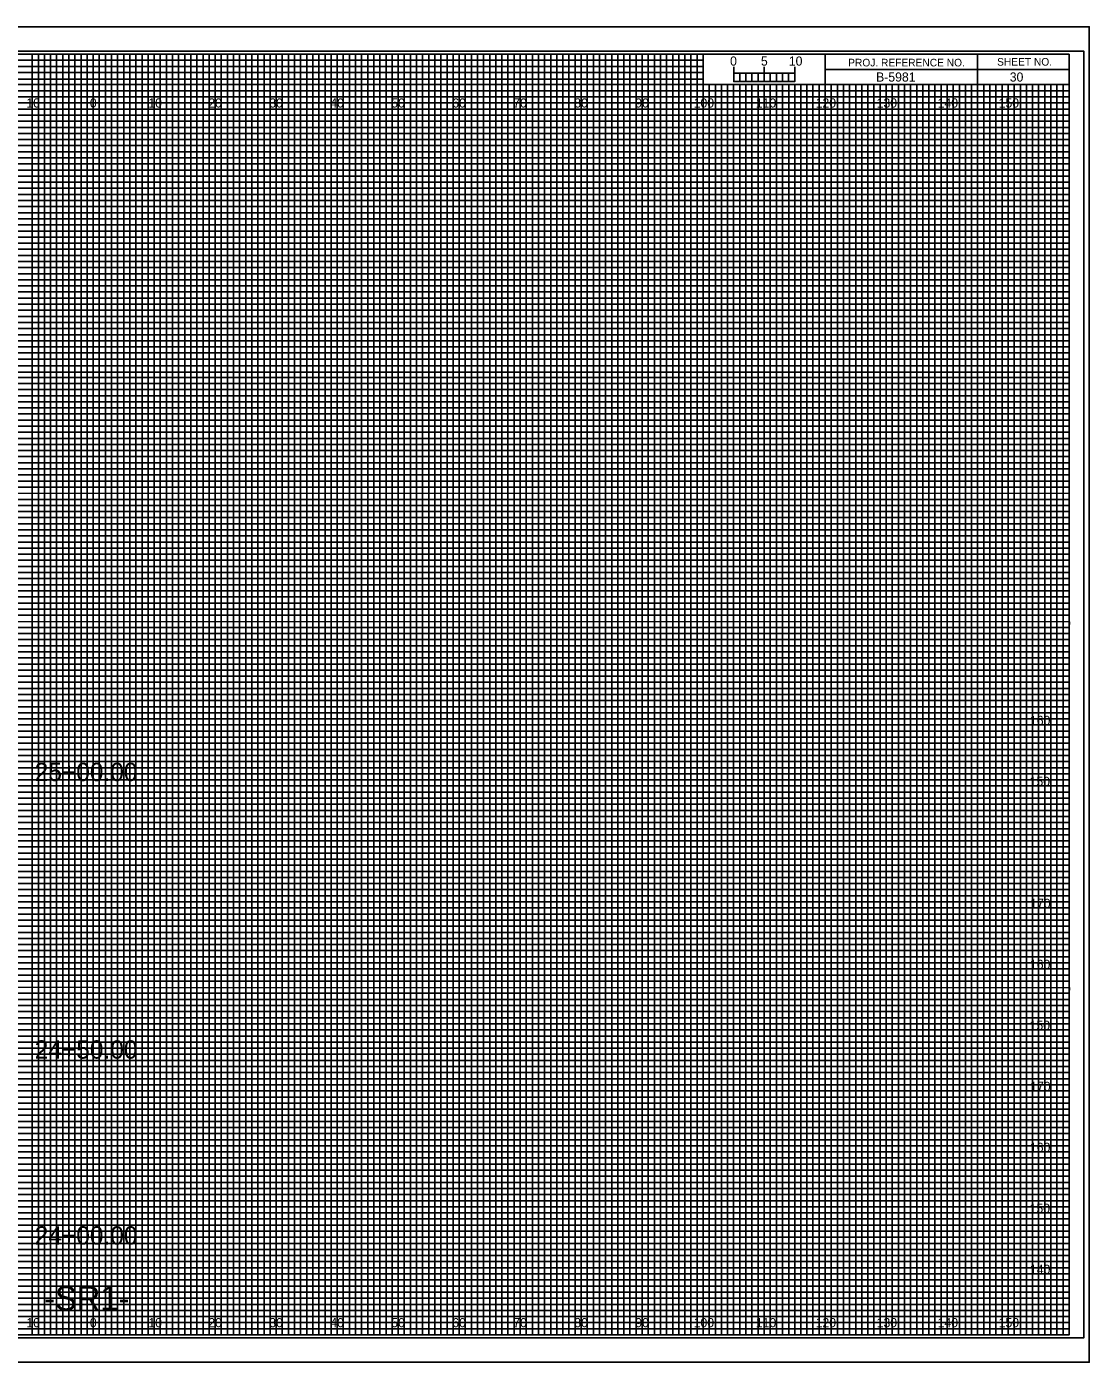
# Model space of a CAD drawing. Extents: x -13 to 323, y -5 to 654.
# Drawn here: x 149.1 to 323.3, y 435.5 to 654.5 of the extents above; entities that cross this region are included whole.
import ezdxf

# ---------------------------------------------------------------- set-up
doc = ezdxf.new("R2010")
doc.units = 0
for name, color, linetype in [('Exist Cross Section Cell', 7, 'Continuous'), ('Exist XS Center Line Elevation Label', 7, 'Continuous'), ('Exist XS Ground Line', 7, 'Continuous'), ('Prop CMT Concrete Structures', 7, 'Continuous'), ('Prop CMT Guardrail Graphics', 7, 'Continuous'), ('Prop CMT Pvmt Course 1', 7, 'Continuous'), ('Prop CMT Pvmt Course 2', 7, 'Continuous'), ('Prop CMT Pvmt Course 3', 7, 'Continuous'), ('Prop CMT Pvmt Surface', 7, 'Continuous'), ('Prop CMT Shld Paved Course 1', 7, 'Continuous'), ('Prop CMT Shld Paved Course 2', 7, 'Continuous'), ('Prop CMT Shld Paved Course 3', 7, 'Continuous'), ('Prop CMT Subgrade Earthwork', 7, 'Continuous'), ('Prop XS Ditch Standard Text', 7, 'Continuous'), ('Prop XS SE Text', 7, 'Continuous'), ('Prop XS Side Slope Text', 7, 'Continuous'), ('Scratch_Level_0', 7, 'Continuous')]:
    doc.layers.add(name, color=color, linetype=linetype)

msp = doc.modelspace()

# ---------------------------------------------------------------- linework, layer by layer
at = {"layer": 'Exist XS Center Line Elevation Label'}
for points in [[(145, 440), (155, 440), (155, 650), (165, 650), (165, 440), (175, 440), (175, 650), (185, 650), (185, 440), (195, 440), (195, 650), (205, 650), (205, 440), (215, 440), (215, 650), (225, 650), (225, 440), (235, 440), (235, 650), (245, 650), (245, 440), (255, 440), (255, 650), (259.93, 650), (260, 650), (260, 645), (264.99, 645), (264.99, 440), (275, 440), (275, 645), (285, 645), (285, 440), (295, 440), (295, 645), (305, 645), (305, 440), (315, 440), (315, 645)], [(0, 645), (275, 645)], [(0, 625), (320, 625), (320, 635), (0, 635)], [(0, 605), (320, 605), (320, 615), (0, 615)], [(0, 585), (320, 585), (320, 595), (0, 595)], [(0, 565), (320, 565), (320, 575), (0, 575)], [(0, 545), (320, 545), (320, 555), (0, 555)], [(0, 525), (320, 525), (320, 535), (0, 535)], [(0, 505), (320, 505), (320, 515), (0, 515)], [(0, 485), (320, 485), (320, 495), (0, 495)], [(0, 465), (320, 465), (320, 475), (0, 475)], [(0, 445), (320, 445), (320, 455), (0, 455)]]:
    msp.add_lwpolyline(points, dxfattribs=at)
at = {"layer": 'Exist XS Ground Line'}
for p, q in [((150, 650), (140, 650)), ((150, 440), (150, 650)), ((170, 650), (160, 650)), ((160, 650), (160, 440)), ((170, 440), (170, 650)), ((190, 650), (180, 650)), ((180, 650), (180, 440)), ((190, 440), (190, 650)), ((210, 650), (200, 650)), ((200, 650), (200, 440)), ((210, 440), (210, 650)), ((230, 650), (220, 650)), ((220, 650), (220, 440)), ((230, 440), (230, 650)), ((250, 650), (240, 650)), ((240, 650), (240, 440)), ((250, 440), (250, 650)), ((260, 650), (260, 440)), ((270, 440), (270, 645)), ((290, 645), (280, 645)), ((280, 645), (280, 440)), ((290, 440), (290, 645)), ((310, 645), (300, 645)), ((300, 645), (300, 440)), ((310, 440), (310, 645)), ((160, 440), (150, 440)), ((180, 440), (170, 440)), ((200, 440), (190, 440)), ((220, 440), (210, 440)), ((240, 440), (230, 440)), ((260, 440), (250, 440)), ((280, 440), (270, 440)), ((300, 440), (290, 440)), ((320, 440), (310, 440)), ((320, 440), (320, 440))]:
    msp.add_line(p, q, dxfattribs=at)
for points in [[(0, 640), (320, 640), (320, 630), (0, 630)], [(0, 620), (320, 620), (320, 610), (0, 610)], [(0, 600), (320, 600), (320, 590), (0, 590)], [(0, 580), (320, 580), (320, 570), (0, 570)], [(0, 560), (320, 560), (320, 550), (0, 550)], [(0, 540), (320, 540), (320, 530), (0, 530)], [(0, 520), (320, 520), (320, 510), (0, 510)], [(0, 500), (320, 500), (320, 490), (0, 490)], [(0, 480), (320, 480), (320, 470), (0, 470)], [(0, 460), (320, 460), (320, 450), (0, 450)]]:
    msp.add_lwpolyline(points, dxfattribs=at)
at = {"layer": 'Prop CMT Pvmt Course 1'}
for p, q in [((323.3, 654.5), (-13.4, 654.5)), ((-13.4, 435.5), (323.3, 435.5))]:
    msp.add_line(p, q, dxfattribs=at)
at = {"layer": 'Prop CMT Pvmt Course 2'}
msp.add_lwpolyline([(-13.4, 435.5), (323.3, 435.5), (323.3, 654.5), (-13.4, 654.5)], close=True, dxfattribs=at)
at = {"layer": 'Prop CMT Pvmt Course 3'}
msp.add_lwpolyline([(-10.8, 439.5), (322.4, 439.5), (322.4, 650.5), (-10.8, 650.5)], close=True, dxfattribs=at)
at = {"layer": 'Prop CMT Shld Paved Course 1'}
for p, q in [((305, 650), (305, 645)), ((305, 645), (305, 650)), ((280, 647.5), (280, 645)), ((320, 647.49), (280, 647.49)), ((280, 645), (320, 645))]:
    msp.add_line(p, q, dxfattribs=at)
for points in [[(320, 650), (0, 650), (0, 440), (320, 440)], [(280, 650), (260, 650), (260, 645.03), (280, 645.03)], [(320, 650), (280, 650), (280, 645), (320, 645)]]:
    msp.add_lwpolyline(points, close=True, dxfattribs=at)
at = {"layer": 'Prop CMT Shld Paved Course 2'}
for p, q in [((267, 645), (266.01, 645)), ((266.01, 645), (266.01, 440)), ((267, 440), (267, 645)), ((269, 645), (268, 645)), ((268, 645), (268, 440)), ((269, 440), (269, 645)), ((266.01, 440), (265, 440)), ((268, 440), (267, 440))]:
    msp.add_line(p, q, dxfattribs=at)
for points in [[(150, 440), (151, 440), (151, 650), (152, 650), (152, 440)], [(152, 440), (153, 440), (153, 650), (154, 650), (154, 440)], [(155, 440), (156, 440), (156, 650), (157, 650), (157, 440)], [(157, 440), (158, 440), (158, 650), (159, 650), (159, 440)], [(160, 440), (161, 440), (161, 650), (162, 650), (162, 440)], [(162, 440), (163, 440), (163, 650), (164, 650), (164, 440)], [(165, 440), (166, 440), (166, 650), (167, 650), (167, 440)], [(167, 440), (168, 440), (168, 650), (169, 650), (169, 440)], [(170, 440), (171, 440), (171, 650), (172, 650), (172, 440)], [(172, 440), (173, 440), (173, 650), (174, 650), (174, 440)], [(175, 440), (176, 440), (176, 650), (177, 650), (177, 440)], [(177, 440), (178, 440), (178, 650), (179, 650), (179, 440)], [(180, 440), (181, 440), (181, 650), (182, 650), (182, 440)], [(182, 440), (183, 440), (183, 650), (184, 650), (184, 440)], [(185, 440), (186, 440), (186, 650), (187, 650), (187, 440)], [(187, 440), (188, 440), (188, 650), (189, 650), (189, 440)], [(190, 440), (191, 440), (191, 650), (192, 650), (192, 440)], [(192, 440), (193, 440), (193, 650), (194, 650), (194, 440)], [(195, 440), (196, 440), (196, 650), (197, 650), (197, 440)], [(197, 440), (198, 440), (198, 650), (199, 650), (199, 440)], [(200, 440), (201, 440), (201, 650), (202, 650), (202, 440)], [(202, 440), (203, 440), (203, 650), (204, 650), (204, 440)], [(205, 440), (206, 440), (206, 650), (207, 650), (207, 440)], [(207, 440), (208, 440), (208, 650), (209, 650), (209, 440)], [(210, 440), (211, 440), (211, 650), (212, 650), (212, 440)], [(212, 440), (213, 440), (213, 650), (214, 650), (214, 440)], [(215, 440), (216, 440), (216, 650), (217, 650), (217, 440)], [(217, 440), (218, 440), (218, 650), (219, 650), (219, 440)], [(220, 440), (221, 440), (221, 650), (222, 650), (222, 440)], [(222, 440), (223, 440), (223, 650), (224, 650), (224, 440)], [(225, 440), (226, 440), (226, 650), (227, 650), (227, 440)], [(227, 440), (228, 440), (228, 650), (229, 650), (229, 440)], [(230, 440), (231, 440), (231, 650), (232, 650), (232, 440)], [(232, 440), (233, 440), (233, 650), (234, 650), (234, 440)], [(235, 440), (236, 440), (236, 650), (237, 650), (237, 440)], [(237, 440), (238, 440), (238, 650), (239, 650), (239, 440)], [(240, 440), (241, 440), (241, 650), (242, 650), (242, 440)], [(242, 440), (243, 440), (243, 650), (244, 650), (244, 440)], [(245, 440), (246, 440), (246, 650), (247, 650), (247, 440)], [(247, 440), (248, 440), (248, 650), (249, 650), (249, 440)], [(250, 440), (251, 440), (251, 650), (252, 650), (252, 440)], [(252, 440), (253, 440), (253, 650), (254, 650), (254, 440)], [(255, 440), (256, 440), (256, 650), (257, 650), (257, 440)], [(257, 440), (258, 440), (258, 650), (259, 650), (259, 440)], [(260, 440), (261, 440), (261, 645), (262.02, 645), (262.02, 440)], [(262, 440), (263, 440), (263, 645), (263.99, 645), (263.99, 440)], [(270, 440), (270.98, 440), (270.98, 645), (272, 645), (272, 440)], [(272, 440), (273, 440), (273, 645), (274.05, 645), (274.05, 440)], [(275, 440), (276, 440), (276, 645), (277, 645), (277, 440)], [(277, 440), (278, 440), (278, 645), (279, 645), (279, 440)], [(280, 440), (281, 440), (281, 645), (282, 645), (282, 440)], [(282, 440), (283, 440), (283, 645), (284, 645), (284, 440)], [(285, 440), (286, 440), (286, 645), (287, 645), (287, 440)], [(287, 440), (288, 440), (288, 645), (289, 645), (289, 440)], [(290, 440), (291, 440), (291, 645), (292, 645), (292, 440)], [(292, 440), (293, 440), (293, 645), (294, 645), (294, 440)], [(295, 440), (296, 440), (296, 645), (297, 645), (297, 440)], [(297, 440), (298, 440), (298, 645), (299, 645), (299, 440)], [(300, 440), (301, 440), (301, 645), (302, 645), (302, 440)], [(302, 440), (303, 440), (303, 645), (304, 645), (304, 440)], [(305, 440), (306, 440), (306, 645), (307, 645), (307, 440)], [(307, 440), (308, 440), (308, 645), (309, 645), (309, 440)], [(310, 440), (311, 440), (311, 645), (312, 645), (312, 440)], [(312, 440), (313, 440), (313, 645), (314, 645), (314, 440)], [(315, 440), (316, 440), (316, 645), (317, 645), (317, 440)], [(317, 440), (318, 440), (318, 645), (319, 645), (319, 440)]]:
    msp.add_lwpolyline(points, dxfattribs=at)
at = {"layer": 'Prop CMT Shld Paved Course 3'}
for p, q in [((265, 645.49), (265, 647.9)), ((265, 646.9), (265, 647.9)), ((270, 645.49), (270, 647.9)), ((275, 645.49), (275, 647.9)), ((275, 646.9), (275, 647.9))]:
    msp.add_line(p, q, dxfattribs=at)
for points in [[(275, 646.9), (265, 646.9), (265, 645.49), (275, 645.49)], [(265, 646.9), (266, 646.9), (266, 645.49), (265, 645.49)], [(267, 646.9), (268, 646.9), (268, 645.49), (267, 645.49)], [(269, 646.9), (270, 646.9), (270, 645.49), (269, 645.49)], [(271, 646.9), (272, 646.9), (272, 645.49), (271, 645.49)], [(273, 646.9), (274, 646.9), (274, 645.49), (273, 645.49)]]:
    msp.add_lwpolyline(points, close=True, dxfattribs=at)
at = {"layer": 'Prop CMT Subgrade Earthwork'}
for p, q in [((150, 440), (150, 650)), ((160, 440), (160, 650)), ((170, 440), (170, 650)), ((180, 440), (180, 650)), ((190, 440), (190, 650)), ((200, 440), (200, 650)), ((210, 440), (210, 650)), ((220, 440), (220, 650)), ((230, 440), (230, 650)), ((240, 440), (240, 650)), ((250, 440), (250, 650)), ((260, 440), (260, 644.69)), ((270, 440), (270, 644.69)), ((280, 440), (280, 644.69)), ((290, 440), (290, 644.69)), ((300, 440), (300, 644.69)), ((310, 440), (310, 644.69)), ((0, 640), (320, 640)), ((0, 630), (320, 630)), ((0, 620), (320, 620)), ((0, 610), (320, 610)), ((0, 600), (320, 600)), ((0, 590), (320, 590)), ((0, 580), (320, 580)), ((0, 570), (320, 570)), ((0, 560), (320, 560)), ((0, 550), (320, 550)), ((0, 540), (320, 540)), ((0, 530), (320, 530)), ((0, 520), (320, 520)), ((0, 510), (320, 510)), ((0, 500), (320, 500)), ((0, 490), (320, 490)), ((0, 480), (320, 480)), ((0, 470), (320, 470)), ((0, 460), (320, 460)), ((0, 450), (320, 450))]:
    msp.add_line(p, q, dxfattribs=at)
at = {"layer": 'Scratch_Level_0'}
for p, q in [((0, 649), (260, 649)), ((260, 649), (260, 647.98)), ((260, 647.98), (0, 647.98)), ((0, 647), (260, 647)), ((260, 647), (260, 645.89)), ((260, 645.89), (0, 645.89)), ((0, 644), (320, 644))]:
    msp.add_line(p, q, dxfattribs=at)
for points in [[(0, 643), (270, 643), (320, 643), (320, 642), (0, 642)], [(0, 641), (320, 641), (320, 639), (0, 639)], [(0, 638), (320, 638), (320, 637), (0, 636.98)], [(0, 636), (320, 636), (320, 634), (0, 634)], [(0, 633), (320, 633), (320, 632), (0, 632)], [(0, 631), (320, 631), (320, 629), (0, 629)], [(0, 628), (320, 628), (320, 627), (0, 627)], [(0, 626), (320, 626), (320, 624), (0, 624)], [(0, 623), (320, 623), (320, 622), (0, 622)], [(0, 621), (320, 621), (320, 619), (0, 619)], [(0, 618), (320, 618), (320, 617), (0, 617)], [(0, 616), (320, 616), (320, 613.95), (320, 613), (320, 612), (0, 612)], [(0, 614), (320, 614), (320, 613), (0, 613)], [(0, 611), (320, 611), (320, 609), (0, 609.03)], [(0, 609.03), (320, 609), (320, 608), (0, 608)], [(0, 607), (320, 607), (320, 606), (0, 606)], [(0, 604), (320, 604), (320, 603), (0, 603)], [(0, 602), (320, 602), (320, 601), (0, 601)], [(-0.07, 598.89), (320, 598.89), (320, 597.88), (-0.07, 597.88)], [(0, 597), (320, 597), (320, 596), (0, 596)], [(0, 594), (320, 594), (320, 593), (0, 593)], [(0, 592), (320, 592), (320, 591), (0, 591)], [(0, 589), (320, 589), (320, 588), (0, 588)], [(0, 587), (320, 587), (320, 586), (0, 586)], [(0, 584), (320, 584), (320, 583), (0, 583)], [(0, 582), (320, 582), (320, 581), (0, 581)], [(0, 579), (320, 579), (319.99, 577.98), (0, 578)], [(0, 577), (320, 577), (320, 576), (0, 576)], [(0, 574), (320, 574), (320, 573), (0, 573)], [(0, 572), (320, 572), (320, 571), (0, 571)], [(0, 569), (320, 569), (320, 568), (0, 568)], [(0, 567), (320, 567), (320, 566), (0, 566)], [(0, 564), (320, 564), (320, 563), (0, 563)], [(0, 562), (320, 562), (320, 561), (0, 561)], [(0, 559), (320, 559), (320, 558), (0, 558)], [(0, 556.99), (320.07, 556.91), (320, 556), (0, 556)], [(0, 554), (320, 554), (320, 553), (0, 553)], [(0, 552), (320, 552), (320, 551), (0, 551)], [(0, 549), (320, 549), (320, 548), (0, 548)], [(0, 547), (320, 547), (320, 546), (0, 546)], [(0, 544), (320, 544), (320, 543), (0, 543)], [(0, 542), (320, 542), (320, 541), (0, 541)], [(0, 539), (320, 539), (320, 538), (0, 538)], [(0, 537), (320, 537), (320, 536), (0, 536)], [(0, 534), (320, 534), (320, 533), (0, 533)], [(0, 532), (320, 532), (320, 531), (0, 531)], [(0, 529), (320, 529), (320, 528), (0, 528)], [(0, 527), (320, 527), (320, 526), (0, 526)], [(0, 524), (320, 524), (320, 523), (0, 523)], [(0, 522), (320, 522), (320, 521), (0, 521)], [(0, 519), (320, 519), (319.99, 517.98), (0, 518)], [(0, 517), (320, 517), (320, 516), (0, 516)], [(0, 514), (320, 514), (320, 513), (0, 513)], [(0, 512), (320, 512), (320, 511), (0, 511)], [(0, 509), (320, 509), (320, 508), (0, 508)], [(0, 507), (320, 507), (320, 506), (0, 506)], [(0, 504), (320, 504), (320, 503), (0, 503)], [(0, 502), (320, 502), (320, 501), (0, 501)], [(0, 499), (320, 499), (320, 498), (0, 498)], [(0, 496.99), (320.07, 496.91), (320, 496), (0, 496)], [(0, 494), (320, 494), (320, 493), (0, 493)], [(0, 492), (320, 492), (320, 491), (0, 491)], [(0, 489), (320, 489), (320, 488), (0, 488)], [(0, 487), (320, 487), (320, 486), (0, 486)], [(0, 484), (320, 484), (320, 483), (0, 483)], [(0, 482), (320, 482), (320, 481), (0, 481)], [(0, 479), (320, 479), (320, 478), (0, 478)], [(0, 477), (320, 477), (320, 476), (0, 476)], [(0, 474), (320, 474), (320, 473), (0, 473)], [(0, 472), (320, 472), (320, 471), (0, 471)], [(0, 469), (320, 469), (320, 468), (0, 468)], [(0, 467), (320, 467), (320, 466), (0, 466)], [(0, 464), (320, 464), (320, 463), (0, 463)], [(0, 462), (320, 462), (320, 461), (0, 461)], [(0, 459), (320, 459), (320, 458), (0, 458)], [(0, 457), (320, 457), (320, 456), (0, 456)], [(0, 454), (320, 454), (320, 453), (0, 453)], [(0, 452), (320, 452), (320, 451), (0, 451)], [(0, 449), (320, 449), (320, 448), (0, 448)], [(0, 447), (320, 447), (320, 446), (0, 446)], [(0, 444), (320, 444), (320, 443), (0, 443)], [(0, 442), (320, 442), (320, 441), (0, 441)]]:
    msp.add_lwpolyline(points, dxfattribs=at)

# ---------------------------------------------------------------- texts
at = {"layer": 'Exist Cross Section Cell'}
for s, p in [('10', (149.04, 641.25)), ('0', (159.45, 641.25)), ('0', (159.45, 641.25)), ('10', (169.04, 641.25)), ('20', (178.86, 641.25)), ('30', (188.86, 641.25)), ('40', (198.86, 641.25)), ('50', (208.86, 641.25)), ('60', (218.86, 641.25)), ('70', (228.86, 641.25)), ('80', (238.86, 641.25)), ('90', (248.86, 641.25)), ('100', (258.44, 641.25)), ('110', (268.62, 641.25)), ('120', (278.44, 641.25)), ('130', (288.44, 641.25)), ('140', (298.44, 641.25)), ('150', (308.44, 641.25)), ('10', (149.04, 441.25)), ('0', (159.45, 441.25)), ('0', (159.45, 441.25)), ('10', (169.04, 441.25)), ('20', (178.86, 441.25)), ('30', (188.86, 441.25)), ('40', (198.86, 441.25)), ('50', (208.86, 441.25)), ('60', (218.86, 441.25)), ('70', (228.86, 441.25)), ('80', (238.86, 441.25)), ('90', (248.86, 441.25)), ('100', (258.44, 441.25)), ('110', (268.62, 441.25)), ('120', (278.44, 441.25)), ('130', (288.44, 441.25)), ('140', (298.44, 441.25)), ('150', (308.44, 441.25))]:
    msp.add_text(s, height=1.5, dxfattribs=at).set_placement(p)
at = {"layer": 'Prop CMT Concrete Structures'}
for s, p in [('25+00.00', (150.41, 530.8)), ('24+50.00', (150.41, 485.29)), ('24+00.00', (150.41, 454.8))]:
    msp.add_text(s, height=3, dxfattribs=at).set_placement(p)
at = {"layer": 'Prop CMT Guardrail Graphics'}
for s, p in [('160', (313.57, 540)), ('150', (313.52, 530)), ('170', (313.61, 510)), ('160', (313.57, 500)), ('150', (313.52, 490)), ('170', (313.61, 480)), ('160', (313.57, 470)), ('150', (313.52, 460)), ('140', (313.57, 450))]:
    msp.add_text(s, height=1.5, dxfattribs=at).set_placement(p)
at = {"layer": 'Prop CMT Pvmt Surface'}
for s, p in [('5', (269.47, 648.12)), ('10', (274.04, 648.12))]:
    msp.add_text(s, height=1.5, dxfattribs=at).set_placement(p)
at = {"layer": 'Prop CMT Shld Paved Course 1'}
for s, p in [('PROJ. REFERENCE NO.', (283.77, 647.99)), ('SHEET NO.', (308.19, 648.12))]:
    msp.add_text(s, height=1.25, dxfattribs=at).set_placement(p)
at = {"layer": 'Prop CMT Shld Paved Course 3'}
msp.add_text('0', height=1.5, dxfattribs=at).set_placement((264.41, 648.12))
at = {"layer": 'Prop XS Ditch Standard Text'}
msp.add_text('-SR1-', height=4, dxfattribs=at).set_placement((151.95, 444))
at = {"layer": 'Prop XS SE Text'}
msp.add_text(' B-5981', height=1.5, dxfattribs=at).set_placement((287.79, 645.5))
at = {"layer": 'Prop XS Side Slope Text'}
msp.add_text('30', height=1.5, dxfattribs=at).set_placement((310.26, 645.5))

doc.saveas('drawing.dxf')
